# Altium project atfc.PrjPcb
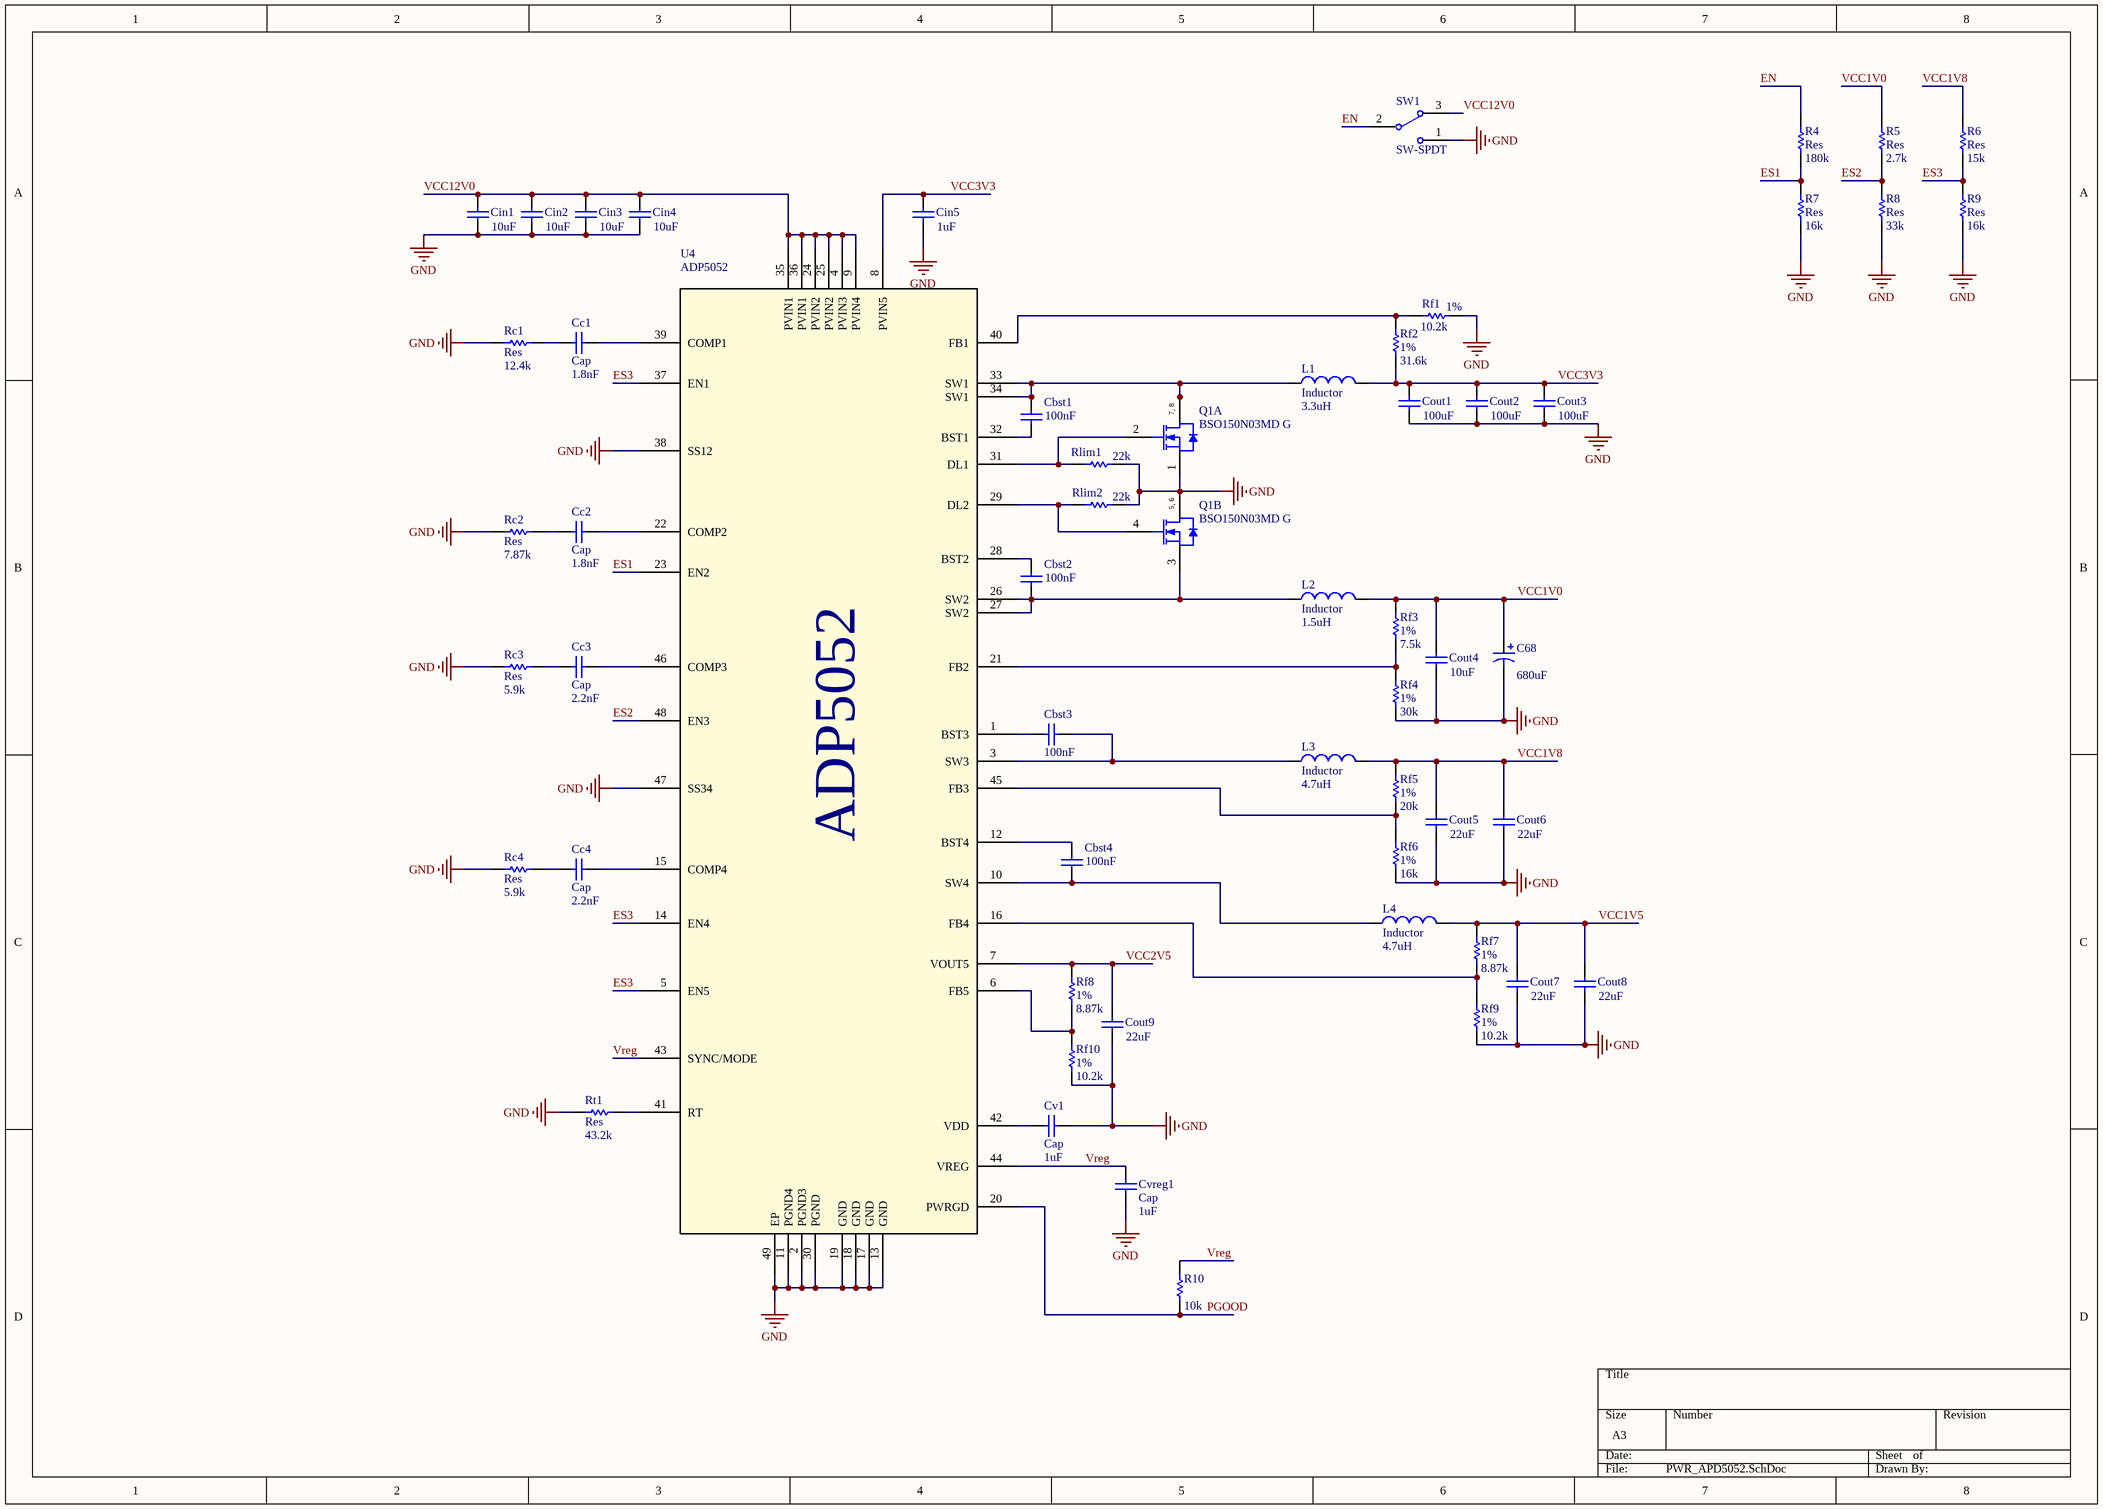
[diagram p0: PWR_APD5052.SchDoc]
9 sheets, 225 parts. Net scope: global (net labels, ports and power ports of the same name join across sheets).
Board file: atfc.PcbDoc
Sheets:
  PWR_APD5052.SchDoc
  FPGA_PWR.SchDoc
  SFP.SchDoc
  IO.SchDoc
  FMC.SchDoc
  FPGA_Banks1.SchDoc
  FPGA_Banks2.SchDoc
  Regulators.SchDoc
  Config.SchDoc

## Sheet PWR_APD5052.SchDoc
size A3

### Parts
C68  value 680uF  [C0805]  (hidden comment: Cap Pol3)
Cbst1  value 100nF  [C0402]  (hidden comment: Cap)
Cbst2  value 100nF  [C0402]  (hidden comment: Cap)
Cbst3  value 100nF  [C0402]  (hidden comment: Cap)
Cbst4  value 100nF  [C0402]  (hidden comment: Cap)
Cc1  Cap  value 1.8nF  [C0805]
Cc2  Cap  value 1.8nF  [C0805]
Cc3  Cap  value 2.2nF  [C0805]
Cc4  Cap  value 2.2nF  [C0805]
Cin1  value 10uF  [C0805]
Cin2  value 10uF  [C0805]
Cin3  value 10uF  [C0805]  (hidden comment: Cap)
Cin4  value 10uF  [C1210]  (hidden comment: Cap)
Cin5  value 1uF  [C0603]
Cout1  value 100uF  [C1210]  (hidden comment: Cap)
Cout2  value 100uF  [C1210]  (hidden comment: Cap)
Cout3  value 100uF  [C1210]  (hidden comment: Cap)
Cout4  value 10uF  [C1210]  (hidden comment: Cap)
Cout5  value 22uF  [C1210]  (hidden comment: Cap)
Cout6  value 22uF  [C1210]  (hidden comment: Cap)
Cout7  value 22uF  [C1210]  (hidden comment: Cap)
Cout8  value 22uF  [C1210]  (hidden comment: Cap)
Cout9  value 22uF  [C1210]  (hidden comment: Cap)
Cv1  Cap  value 1uF  [C0402]
Cvreg1  Cap  value 1uF  [C0402]
L1  Inductor  value 3.3uH  [MSS1048]
L2  Inductor  value 1.5uH  [MSS1048]
L3  Inductor  value 4.7uH  [MSS1048]
L4  Inductor  value 4.7uH  [MSS1048]
Q1  BSO150N03MD G  [INF-PG-DSO-8-16_N]  (parts A,B of 2)
R4  Res  value 180k  [R0603]
R5  Res  value 2.7k  [R0603]
R6  Res  value 15k  [R0603]
R7  Res  value 16k  [R0603]
R8  Res  value 33k  [R0603]
R9  Res  value 16k  [R0603]
R10  value 10k  [R0402]  (hidden comment: Res)
Rc1  Res  value 12.4k  [R0805]
Rc2  Res  value 7.87k  [R0805]
Rc3  Res  value 5.9k  [R0805]
Rc4  Res  value 5.9k  [R0805]
Rf1  value 10.2k  Tolerance: 1%  [R0402]  (hidden comment: Res)
Rf2  value 31.6k  Tolerance: 1%  [R0402]  (hidden comment: Res)
Rf3  value 7.5k  Tolerance: 1%  [R0402]  (hidden comment: Res)
Rf4  value 30k  Tolerance: 1%  [R0402]  (hidden comment: Res)
Rf5  value 20k  Tolerance: 1%  [R0402]  (hidden comment: Res)
Rf6  value 16k  Tolerance: 1%  [R0402]  (hidden comment: Res)
Rf7  value 8.87k  Tolerance: 1%  [R0402]  (hidden comment: Res)
Rf8  value 8.87k  Tolerance: 1%  [R0402]  (hidden comment: Res)
Rf9  value 10.2k  Tolerance: 1%  [R0402]  (hidden comment: Res)
Rf10  value 10.2k  Tolerance: 1%  [R0402]  (hidden comment: Res)
Rlim1  value 22k  [R0805]  (hidden comment: Res)
Rlim2  value 22k  [R0805]  (hidden comment: Res)
Rt1  Res  value 43.2k  [R0805]
SW1  SW-SPDT  [TL36WW15050]
U4  ADP5052  [CP_48_13]

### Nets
GND: C68.2 Cin1.1 Cin2.1 Cin3.1 Cin4.1 Cin5.1 Cout1.1 Cout2.1 Cout3.1 Cout4.1 Cout5.1 Cout6.1 Cout7.1 Cout8.1 Cout9.1 Cv1.1 Cvreg1.1 Q1.1(S1) Q1.5(D2) Q1.6(D2) R7.1 R8.1 R9.1 Rc1.1 Rc2.1 Rc3.1 Rc4.1 Rf1.2 Rf4.1 Rf6.1 Rf9.1 Rf10.1 Rlim1.2 Rlim2.2 Rt1.1 SW1.1 U4.2(PGND3) U4.11(PGND4) U4.13(GND) U4.17(GND) U4.18(GND) U4.19(GND) U4.30(PGND) U4.38(SS12) U4.47(SS34) U4.49(EP)
EN: R4.2 SW1.2
ES1: R4.1 R7.2 U4.23(EN2)
ES2: R5.1 R8.2 U4.48(EN3)
ES3: R6.1 R9.2 U4.5(EN5) U4.14(EN4) U4.37(EN1)
PGOOD: R10.1 U4.20(PWRGD)
VCC1V0: C68.1 Cout4.2 L2.2 R5.2 Rf3.2
VCC1V5: Cout7.2 Cout8.2 L4.2 Rf7.2
VCC1V8: Cout5.2 Cout6.2 L3.2 R6.2 Rf5.2
VCC2V5: Cout9.2 Rf8.2 U4.7(VOUT5)
VCC3V3: Cin5.2 Cout1.2 Cout2.2 Cout3.2 L1.2 Rf2.1 U4.8(PVIN5)
VCC12V0: Cin1.2 Cin2.2 Cin3.2 Cin4.2 SW1.3 U4.4(PVIN3) U4.9(PVIN4) U4.24(PVIN2) U4.25(PVIN2) U4.35(PVIN1) U4.36(PVIN1)
Vreg: Cvreg1.2 R10.2 U4.43(SYNC/MODE) U4.44(VREG)
NetCbst1_1: Cbst1.1 U4.32(BST1)
NetCbst1_2: Cbst1.2 L1.1 Q1.7(D1) Q1.8(D1) U4.33(SW1) U4.34(SW1)
NetCbst2_1: Cbst2.1 L2.1 Q1.3(S2) U4.26(SW2) U4.27(SW2)
NetCbst2_2: Cbst2.2 U4.28(BST2)
NetCbst3_1: Cbst3.1 L3.1 U4.3(SW3)
NetCbst3_2: Cbst3.2 U4.1(BST3)
NetCbst4_1: Cbst4.1 L4.1 U4.10(SW4)
NetCbst4_2: Cbst4.2 U4.12(BST4)
NetCc1_1: Cc1.1 Rc1.2
NetCc1_2: Cc1.2 U4.39(COMP1)
NetCc2_1: Cc2.1 Rc2.2
NetCc2_2: Cc2.2 U4.22(COMP2)
NetCc3_1: Cc3.1 Rc3.2
NetCc3_2: Cc3.2 U4.46(COMP3)
NetCc4_1: Cc4.1 Rc4.2
NetCc4_2: Cc4.2 U4.15(COMP4)
NetCv1_2: Cv1.2 U4.42(VDD)
NetQ1_2: Q1.2(G1) Rlim1.1 U4.31(DL1)
NetQ1_4: Q1.4(G2) Rlim2.1 U4.29(DL2)
NetRf1_1: Rf1.1 Rf2.2 U4.40(FB1)
NetRf3_1: Rf3.1 Rf4.2 U4.21(FB2)
NetRf5_1: Rf5.1 Rf6.2 U4.45(FB3)
NetRf7_1: Rf7.1 Rf9.2 U4.16(FB4)
NetRf8_1: Rf8.1 Rf10.2 U4.6(FB5)
NetRt1_2: Rt1.2 U4.41(RT)

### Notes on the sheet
- (near U4) ADP5052

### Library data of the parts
C68 = Cap Pol3: Polarized Capacitor (Surface Mount)
Cbst1-Cbst4 Cc1-Cc4 Cin1-Cin5 Cout1-Cout9 Cv1 Cvreg1 = Cap: Capacitor
L1-L4 = Inductor: Code_IEC: 1005
Q1 = BSO150N03MD G: N-Channel OptiMOS 3 M-Series Power-MOSFET, 30 V VDS, 9.3 A ID, -55 to 150 degC, PG-DSO-8-16, Reel, Green; Manufacturer: Infineon; Green: TRUE; ID (max): 9.3 A; IDpuls (max): 65 A; Polarity: N; Ptot (max): 2 W; QG: 6.1 nC; RDS (on) (max): 15 mOhm; RDS (on) (max) (@4.5V): 18.2 mOhm; Rth: 50 K/W; RthJA (max): 150 K/W; VDS (max): 30 V; VGS(th) (max): 2 V; VGS(th) (min): 1 V
R4-R10 Rc1-Rc4 Rf1-Rf10 Rlim1 Rlim2 Rt1 = Res: Resistor
SW1 = SW-SPDT: SPDT Subminiature Toggle Switch, Right Angle Mounting, Vertical Actuation
U4 = ADP5052ACPZ-R7: Imported

## Sheet FPGA_PWR.SchDoc
size A4
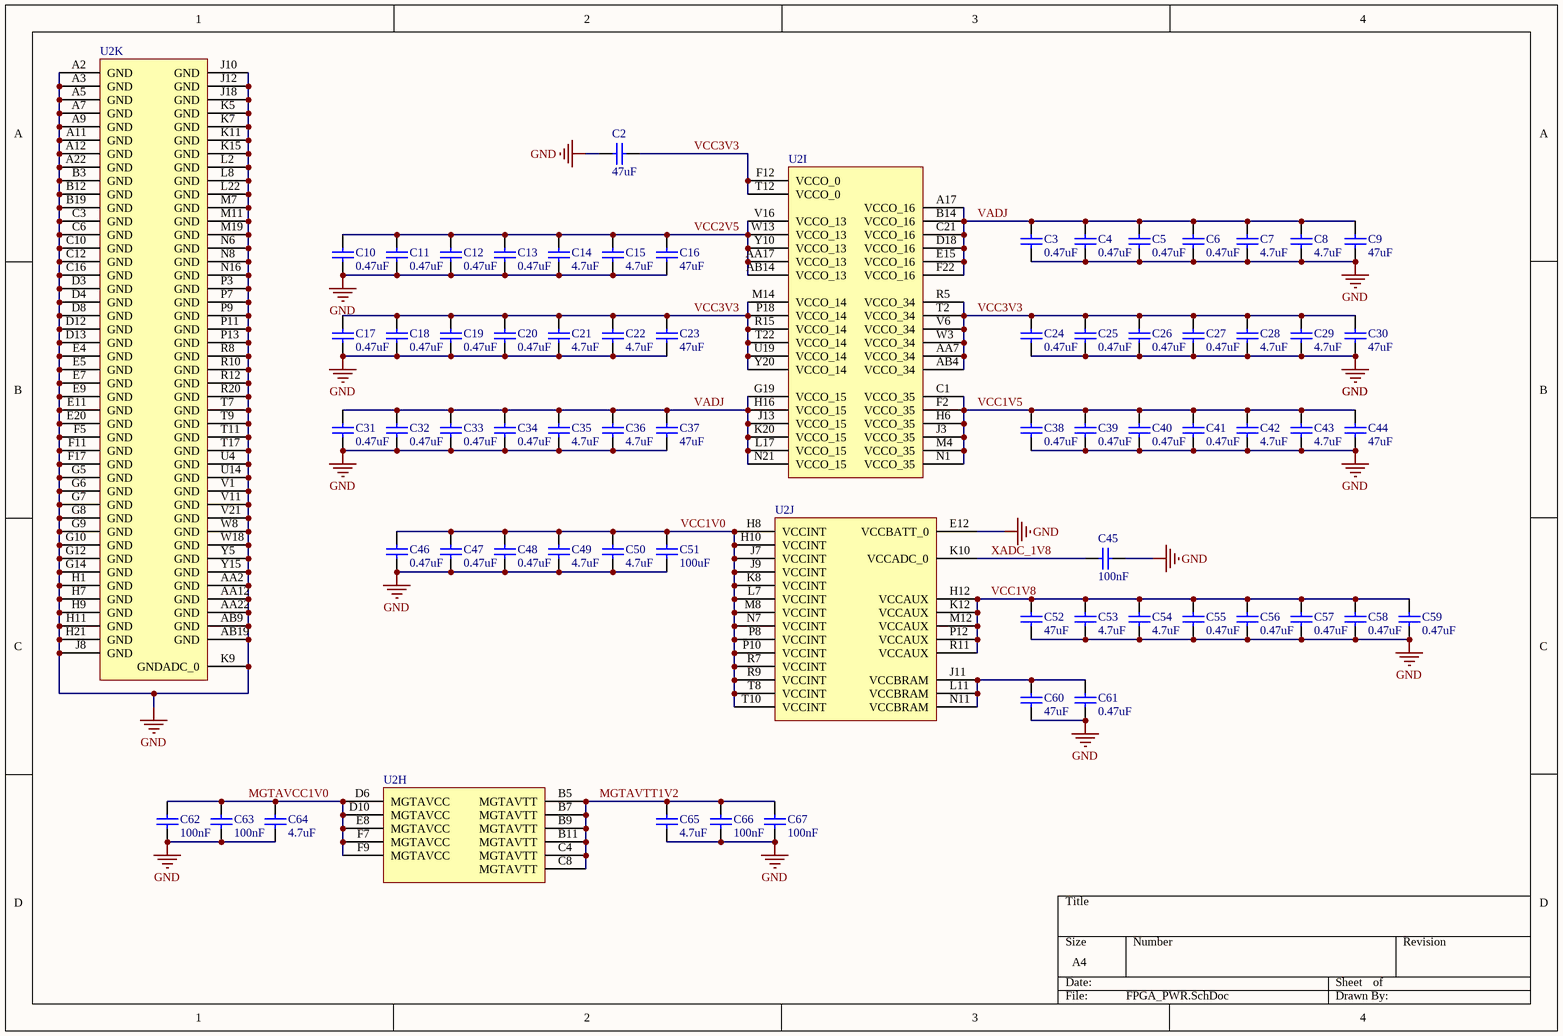
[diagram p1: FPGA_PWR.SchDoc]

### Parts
C2  value 47uF  [C1210]  (hidden comment: Cap)
C3  value 0.47uF  [C0603]  (hidden comment: Cap)
C4  value 0.47uF  [C0603]  (hidden comment: Cap)
C5  value 0.47uF  [C0603]  (hidden comment: Cap)
C6  value 0.47uF  [C0603]  (hidden comment: Cap)
C7  value 4.7uF  [C0805]  (hidden comment: Cap)
C8  value 4.7uF  [C0805]  (hidden comment: Cap)
C9  value 47uF  [C1210]  (hidden comment: Cap)
C10  value 0.47uF  [C0603]  (hidden comment: Cap)
C11  value 0.47uF  [C0603]  (hidden comment: Cap)
C12  value 0.47uF  [C0603]  (hidden comment: Cap)
C13  value 0.47uF  [C0603]  (hidden comment: Cap)
C14  value 4.7uF  [C0805]  (hidden comment: Cap)
C15  value 4.7uF  [C0805]  (hidden comment: Cap)
C16  value 47uF  [C1210]  (hidden comment: Cap)
C17  value 0.47uF  [C0603]  (hidden comment: Cap)
C18  value 0.47uF  [C0603]  (hidden comment: Cap)
C19  value 0.47uF  [C0603]  (hidden comment: Cap)
C20  value 0.47uF  [C0603]  (hidden comment: Cap)
C21  value 4.7uF  [C0805]  (hidden comment: Cap)
C22  value 4.7uF  [C0805]  (hidden comment: Cap)
C23  value 47uF  [C1210]  (hidden comment: Cap)
C24  value 0.47uF  [C0603]  (hidden comment: Cap)
C25  value 0.47uF  [C0603]  (hidden comment: Cap)
C26  value 0.47uF  [C0603]  (hidden comment: Cap)
C27  value 0.47uF  [C0603]  (hidden comment: Cap)
C28  value 4.7uF  [C0805]  (hidden comment: Cap)
C29  value 4.7uF  [C0805]  (hidden comment: Cap)
C30  value 47uF  [C1210]  (hidden comment: Cap)
C31  value 0.47uF  [C0603]  (hidden comment: Cap)
C32  value 0.47uF  [C0603]  (hidden comment: Cap)
C33  value 0.47uF  [C0603]  (hidden comment: Cap)
C34  value 0.47uF  [C0603]  (hidden comment: Cap)
C35  value 4.7uF  [C0805]  (hidden comment: Cap)
C36  value 4.7uF  [C0805]  (hidden comment: Cap)
C37  value 47uF  [C1210]  (hidden comment: Cap)
C38  value 0.47uF  [C0603]  (hidden comment: Cap)
C39  value 0.47uF  [C0603]  (hidden comment: Cap)
C40  value 0.47uF  [C0603]  (hidden comment: Cap)
C41  value 0.47uF  [C0603]  (hidden comment: Cap)
C42  value 4.7uF  [C0805]  (hidden comment: Cap)
C43  value 4.7uF  [C0805]  (hidden comment: Cap)
C44  value 47uF  [C1210]  (hidden comment: Cap)
C45  value 100nF  [C0603]  (hidden comment: Cap)
C46  value 0.47uF  [C0603]  (hidden comment: Cap)
C47  value 0.47uF  [C0603]  (hidden comment: Cap)
C48  value 0.47uF  [C0603]  (hidden comment: Cap)
C49  value 4.7uF  [C0805]  (hidden comment: Cap)
C50  value 4.7uF  [C0805]  (hidden comment: Cap)
C51  value 100uF  [C1210]  (hidden comment: Cap)
C52  value 47uF  [C1210]  (hidden comment: Cap)
C53  value 4.7uF  [C0805]  (hidden comment: Cap)
C54  value 4.7uF  [C0805]  (hidden comment: Cap)
C55  value 0.47uF  [C0603]  (hidden comment: Cap)
C56  value 0.47uF  [C0603]  (hidden comment: Cap)
C57  value 0.47uF  [C0603]  (hidden comment: Cap)
C58  value 0.47uF  [C0603]  (hidden comment: Cap)
C59  value 0.47uF  [C0603]  (hidden comment: Cap)
C60  value 47uF  [C1210]  (hidden comment: Cap)
C61  value 0.47uF  [C0603]  (hidden comment: Cap)
C62  value 100nF  [C0402]  (hidden comment: Cap)
C63  value 100nF  [C0402]  (hidden comment: Cap)
C64  value 4.7uF  [C0805]  (hidden comment: Cap)
C65  value 4.7uF  [C0805]  (hidden comment: Cap)
C66  value 100nF  [C0402]  (hidden comment: Cap)
C67  value 100nF  [C0402]  (hidden comment: Cap)
U2  (no value)  [FGG484]  (parts H,I,J,K of 12)

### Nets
GND: C2.2 C3.2 C4.2 C5.2 C6.2 C7.2 C8.2 C9.2 C10.2 C11.2 C12.2 C13.2 C14.2 C15.2 C16.2 C17.2 C18.2 C19.2 C20.2 C21.2 C22.2 C23.2 C24.2 C25.2 C26.2 C27.2 C28.2 C29.2 C30.2 C31.2 C32.2 C33.2 C34.2 C35.2 C36.2 C37.2 C38.2 C39.2 C40.2 C41.2 C42.2 C43.2 C44.2 C45.1 C46.2 C47.2 C48.2 C49.2 C50.2 C51.2 C52.2 C53.2 C54.2 C55.2 C56.2 C57.2 C58.2 C59.2 C60.2 C61.2 C62.2 C63.2 C64.2 C65.1 C66.1 C67.1 U2.A2(GND) U2.A3(GND) U2.A5(GND) U2.A7(GND) U2.A9(GND) U2.A11(GND) U2.A12(GND) U2.A22(GND) U2.AA2(GND) U2.AA12(GND) U2.AA22(GND) U2.AB9(GND) U2.AB19(GND) U2.B3(GND) U2.B12(GND) U2.B19(GND) U2.C3(GND) U2.C6(GND) U2.C10(GND) U2.C12(GND) U2.C16(GND) U2.D3(GND) U2.D4(GND) U2.D8(GND) U2.D12(GND) U2.D13(GND) U2.E4(GND) U2.E5(GND) U2.E7(GND) U2.E9(GND) U2.E11(GND) U2.E12(VCCBATT_0) U2.E20(GND) U2.F5(GND) U2.F11(GND) U2.F17(GND) U2.G5(GND) U2.G6(GND) U2.G7(GND) U2.G8(GND) U2.G9(GND) U2.G10(GND) U2.G12(GND) U2.G14(GND) U2.H1(GND) U2.H7(GND) U2.H9(GND) U2.H11(GND) U2.H21(GND) U2.J8(GND) U2.J10(GND) U2.J12(GND) U2.J18(GND) U2.K5(GND) U2.K7(GND) U2.K9(GNDADC_0) U2.K11(GND) U2.K15(GND) U2.L2(GND) U2.L8(GND) U2.L22(GND) U2.M7(GND) U2.M11(GND) U2.M19(GND) U2.N6(GND) U2.N8(GND) U2.N16(GND) U2.P3(GND) U2.P7(GND) U2.P9(GND) U2.P11(GND) U2.P13(GND) U2.R8(GND) U2.R10(GND) U2.R12(GND) U2.R20(GND) U2.T7(GND) U2.T9(GND) U2.T11(GND) U2.T17(GND) U2.U4(GND) U2.U14(GND) U2.V1(GND) U2.V11(GND) U2.V21(GND) U2.W8(GND) U2.W18(GND) U2.Y5(GND) U2.Y15(GND)
MGTAVCC1V0: C62.1 C63.1 C64.1 U2.D6(MGTAVCC) U2.D10(MGTAVCC) U2.E8(MGTAVCC) U2.F7(MGTAVCC) U2.F9(MGTAVCC)
MGTAVTT1V2: C65.2 C66.2 C67.2 U2.B5(MGTAVTT) U2.B7(MGTAVTT) U2.B9(MGTAVTT) U2.B11(MGTAVTT) U2.C4(MGTAVTT) U2.C8(MGTAVTT)
VADJ: C3.1 C4.1 C5.1 C6.1 C7.1 C8.1 C9.1 C31.1 C32.1 C33.1 C34.1 C35.1 C36.1 C37.1 U2.A17(VCCO_16) U2.B14(VCCO_16) U2.C21(VCCO_16) U2.D18(VCCO_16) U2.E15(VCCO_16) U2.F22(VCCO_16) U2.G19(VCCO_15) U2.H16(VCCO_15) U2.J13(VCCO_15) U2.K20(VCCO_15) U2.L17(VCCO_15) U2.N21(VCCO_15)
VCC1V0: C46.1 C47.1 C48.1 C49.1 C50.1 C51.1 U2.H8(VCCINT) U2.H10(VCCINT) U2.J7(VCCINT) U2.J9(VCCINT) U2.K8(VCCINT) U2.L7(VCCINT) U2.M8(VCCINT) U2.N7(VCCINT) U2.P8(VCCINT) U2.P10(VCCINT) U2.R7(VCCINT) U2.R9(VCCINT) U2.T8(VCCINT) U2.T10(VCCINT)
VCC1V5: C38.1 C39.1 C40.1 C41.1 C42.1 C43.1 C44.1 U2.C1(VCCO_35) U2.F2(VCCO_35) U2.H6(VCCO_35) U2.J3(VCCO_35) U2.M4(VCCO_35) U2.N1(VCCO_35)
VCC1V8: C52.1 C53.1 C54.1 C55.1 C56.1 C57.1 C58.1 C59.1 U2.H12(VCCAUX) U2.K12(VCCAUX) U2.M12(VCCAUX) U2.P12(VCCAUX) U2.R11(VCCAUX)
VCC2V5: C10.1 C11.1 C12.1 C13.1 C14.1 C15.1 C16.1 U2.AA17(VCCO_13) U2.AB14(VCCO_13) U2.V16(VCCO_13) U2.W13(VCCO_13) U2.Y10(VCCO_13)
VCC3V3: C2.1 C17.1 C18.1 C19.1 C20.1 C21.1 C22.1 C23.1 C24.1 C25.1 C26.1 C27.1 C28.1 C29.1 C30.1 U2.AA7(VCCO_34) U2.AB4(VCCO_34) U2.F12(VCCO_0) U2.M14(VCCO_14) U2.P18(VCCO_14) U2.R5(VCCO_34) U2.R15(VCCO_14) U2.T2(VCCO_34) U2.T12(VCCO_0) U2.T22(VCCO_14) U2.U19(VCCO_14) U2.V6(VCCO_34) U2.W3(VCCO_34) U2.Y20(VCCO_14)
XADC_1V8: C45.2 U2.K10(VCCADC_0)
NetC60_1: C60.1 C61.1 U2.J11(VCCBRAM) U2.L11(VCCBRAM) U2.N11(VCCBRAM)

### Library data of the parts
C2-C67 = Cap: Capacitor
U2 = XC7A35T-1FGG484C: Artix-7 FPGA, 250 User I/Os, 4 GTP, 484-Ball BGA, Speed Grade 1, Commercial Grade, Pb-Free; Manufacturer: Xilinx; Total Block RAM: 1800 Kb; GTP: 4; Clock Mgmt Tiles (CMTs): 5; Logic Cells: 33280; Available User I/O: 250; Speed Grades: 1

## Sheet SFP.SchDoc
size A4
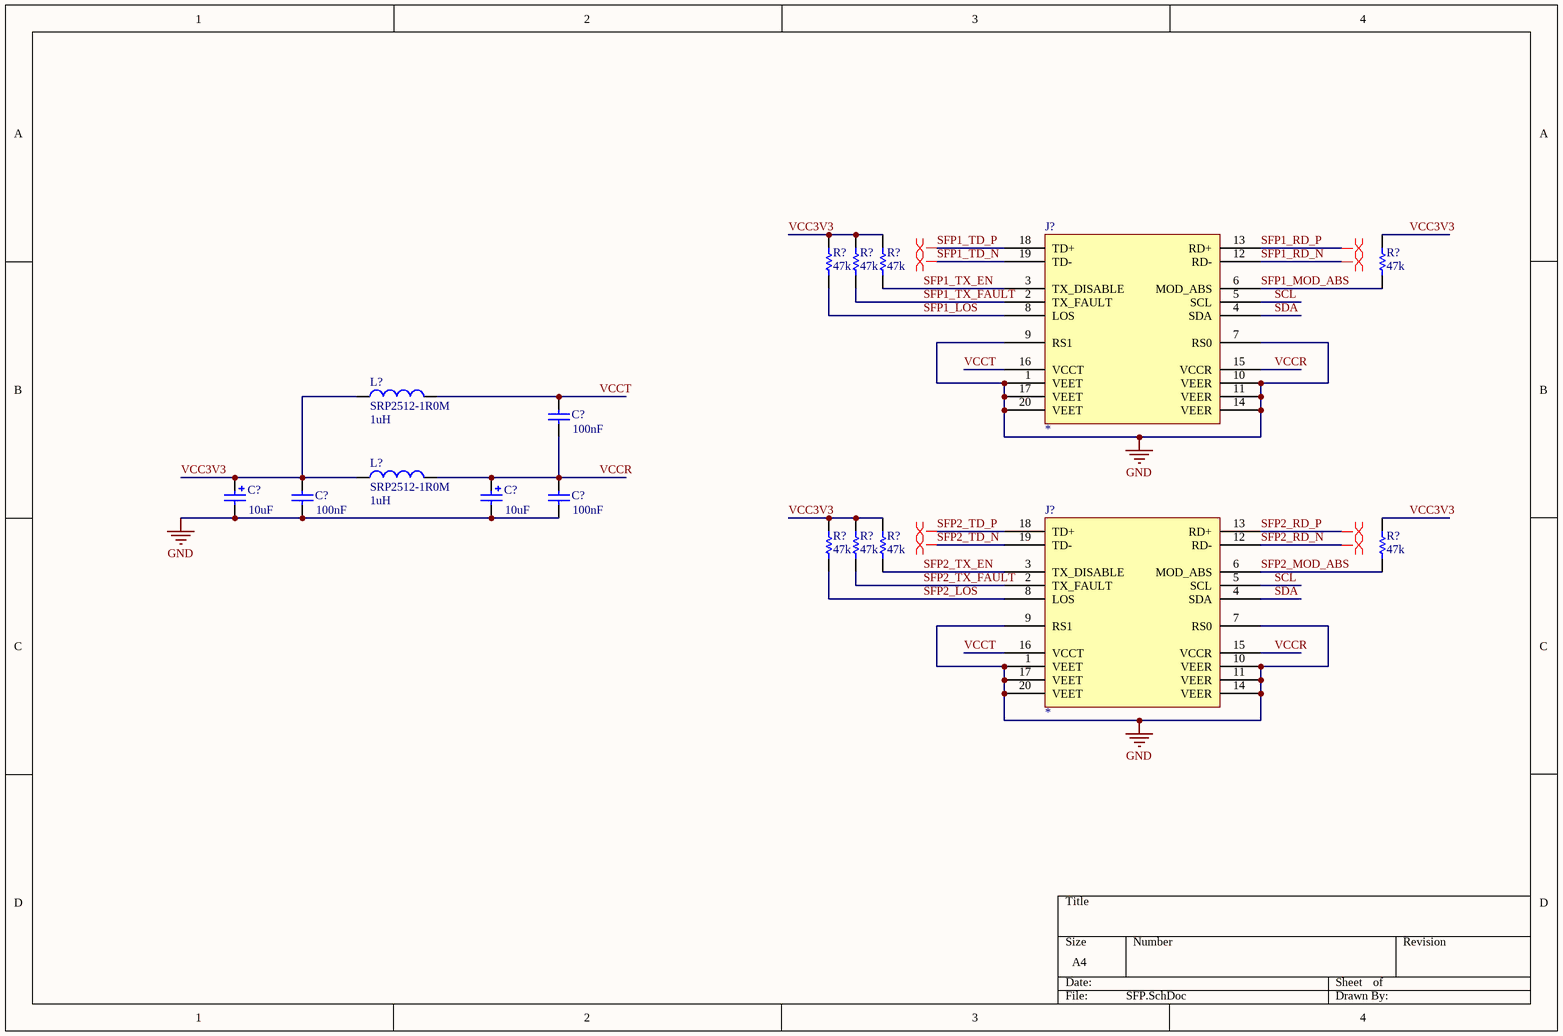
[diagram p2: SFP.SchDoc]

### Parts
(Parts that share a designator on the sheet are numbered #1, #2 ... from top to bottom, then left to right.)
C?#1  value 100nF  [C0402]  (hidden comment: Cap)
C?#2  value 10uF  [C1206_P]
C?#3  value 10uF  [C1206_P]
C?#4  value 100nF  [C0402]  (hidden comment: Cap)
C?#5  value 100nF  [C0402]  (hidden comment: Cap)
J2  *  [SFP+20]
J?  *  [SFP+20]
L?#1  SRP2512-1R0M  value 1uH  [SRP2512]
L?#2  SRP2512-1R0M  value 1uH  [SRP2512]
R?#1  value 47k  [R0402]  (hidden comment: Res)
R?#2  value 47k  [R0402]  (hidden comment: Res)
R?#3  value 47k  [R0402]  (hidden comment: Res)
R?#4  value 47k  [R0402]  (hidden comment: Res)
R?#5  value 47k  [R0402]  (hidden comment: Res)
R?#6  value 47k  [R0402]  (hidden comment: Res)
R?#7  value 47k  [R0402]  (hidden comment: Res)
R?#8  value 47k  [R0402]  (hidden comment: Res)

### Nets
GND: C?#2.2 C?#3.2 C?#4.1 C?#5.1 J2.1(VEET) J2.7(RS0) J2.9(RS1) J2.10(VEER) J2.11(VEER) J2.14(VEER) J2.17(VEET) J2.20(VEET) J?.1(VEET) J?.7(RS0) J?.9(RS1) J?.10(VEER) J?.11(VEER) J?.14(VEER) J?.17(VEET) J?.20(VEET)
SCL: J2.5(SCL) J?.5(SCL)
SDA: J2.4(SDA) J?.4(SDA)
SFP1_LOS: J2.8(LOS) R?#1.2
SFP1_MOD_ABS: J2.6(MOD_ABS) R?#4.2
SFP1_RD_N: J2.12(RD-)
SFP1_RD_P: J2.13(RD+)
SFP1_TD_N: J2.19(TD-)
SFP1_TD_P: J2.18(TD+)
SFP1_TX_EN: J2.3(TX_DISABLE) R?#3.2
SFP1_TX_FAULT: J2.2(TX_FAULT) R?#2.2
SFP2_LOS: J?.8(LOS) R?#5.2
SFP2_MOD_ABS: J?.6(MOD_ABS) R?#8.2
SFP2_RD_N: J?.12(RD-)
SFP2_RD_P: J?.13(RD+)
SFP2_TD_N: J?.19(TD-)
SFP2_TD_P: J?.18(TD+)
SFP2_TX_EN: J?.3(TX_DISABLE) R?#7.2
SFP2_TX_FAULT: J?.2(TX_FAULT) R?#6.2
VCC3V3: C?#2.1 C?#4.2 L?#1.1 L?#2.1 R?#1.1 R?#2.1 R?#3.1 R?#4.1 R?#5.1 R?#6.1 R?#7.1 R?#8.1
VCCR: C?#1.1 C?#3.1 C?#5.2 J2.15(VCCR) J?.15(VCCR) L?#2.2
VCCT: C?#1.2 J2.16(VCCT) J?.16(VCCT) L?#1.2

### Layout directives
differential pair: SFP1_RD_N, SFP1_RD_P, SFP1_TD_N, SFP1_TD_P, SFP2_RD_N, SFP2_RD_P, SFP2_TD_N, SFP2_TD_P

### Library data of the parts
C?#1 C?#4 C?#5 = Cap: Capacitor
C?#2 C?#3 = Cap Pol: Polarized Capacitor (Surface Mount)
J2 J? = SFP+
L?#1 L?#2 = Inductor: Code_IEC: 1005
R?#1-R?#8 = Res: Resistor

## Sheet IO.SchDoc
size A4
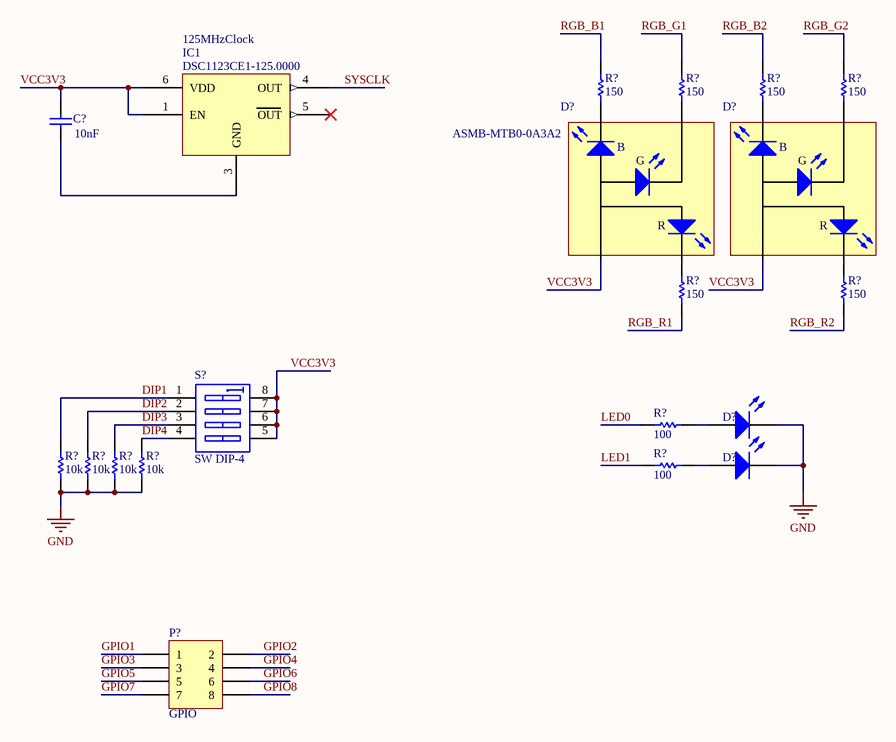
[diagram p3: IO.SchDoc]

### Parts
(Parts that share a designator on the sheet are numbered #1, #2 ... from top to bottom, then left to right.)
C?#6  value 10nF  [C0402]  (hidden comment: Cap)
D?#1  ASMB-MTB0-0A3A2  [ASMB-MTB0-0A3A2]
D?#2  ASMB-MTB0-0A3A2  [ASMB-MTB0-0A3A2]  (value not drawn)
D?#3  LED  (value not drawn)
D?#4  LED  (value not drawn)
IC1  DSC1123CE1-125.0000  [DSC1123_32_25]
P?#1  GPIO  [HDR2X4]
R?#9  value 150  [R0603]  (hidden comment: Res)
R?#10  value 150  [R0603]  (hidden comment: Res)
R?#11  value 150  [R0603]  (hidden comment: Res)
R?#12  value 150  [R0603]  (hidden comment: Res)
R?#13  value 150  [R0603]  (hidden comment: Res)
R?#14  value 150  [R0603]  (hidden comment: Res)
R?#15  value 100  [R0603]  (hidden comment: Res)
R?#16  value 10k  [R0402]  (hidden comment: Res)
R?#17  value 10k  [R0402]  (hidden comment: Res)
R?#18  value 10k  [R0402]  (hidden comment: Res)
R?#19  value 10k  [R0402]  (hidden comment: Res)
R?#20  value 100  [R0603]  (hidden comment: Res)
S?  SW DIP-4  [SO8_N]

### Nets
GND: D?#3.2(K) D?#4.2(K) R?#16.2 R?#17.2 R?#18.2 R?#19.2
DIP1: R?#16.1 S?.1(A1)
DIP2: R?#17.1 S?.2(A2)
DIP3: R?#18.1 S?.3(A3)
DIP4: R?#19.1 S?.4(A4)
GPIO1: P?#1.1
GPIO2: P?#1.2
GPIO3: P?#1.3
GPIO4: P?#1.4
GPIO5: P?#1.5
GPIO6: P?#1.6
GPIO7: P?#1.7
GPIO8: P?#1.8
LED0: R?#15.2
LED1: R?#20.2
RGB_B1: R?#9.2
RGB_B2: R?#11.2
RGB_G1: R?#10.2
RGB_G2: R?#12.2
RGB_R1: R?#13.1
RGB_R2: R?#14.1
SYSCLK: IC1.4(OUT)
VCC3V3: C?#6.2 D?#1.1(A) D?#2.1(A) IC1.1(EN) IC1.6(VDD) S?.5(B4) S?.6(B3) S?.7(B2) S?.8(B1)
NetC?#6_1: C?#6.1 IC1.3(GND)
NetD?#1_2: D?#1.2(B) R?#9.1
NetD?#1_3: D?#1.3(G) R?#10.1
NetD?#1_4: D?#1.4(R) R?#13.2
NetD?#2_2: D?#2.2(B) R?#11.1
NetD?#2_3: D?#2.3(G) R?#12.1
NetD?#2_4: D?#2.4(R) R?#14.2
NetD?#3_1: D?#3.1(A) R?#15.1
NetD?#4_1: D?#4.1(A) R?#20.1

Not connected (* = marked no-connect by the designer): IC1 5(OUT)*

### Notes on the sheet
- (near IC1) 125MHzClock

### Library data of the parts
C?#6 = Cap: Capacitor
D?#1 D?#2 = LED_RGB: Typical INFRARED GaAs LED
IC1 = DSC1123CE1-125: Standard Clock Oscillators Oscillator Hi Perf -20C-70C 50ppm
P?#1 = Header 4X2: Header, 4-Pin, Dual row
R?#9-R?#20 = Res: Resistor
S? = SW DIP-4: DIP Switch, 4 Position, SPST

## Sheet FMC.SchDoc
size A4
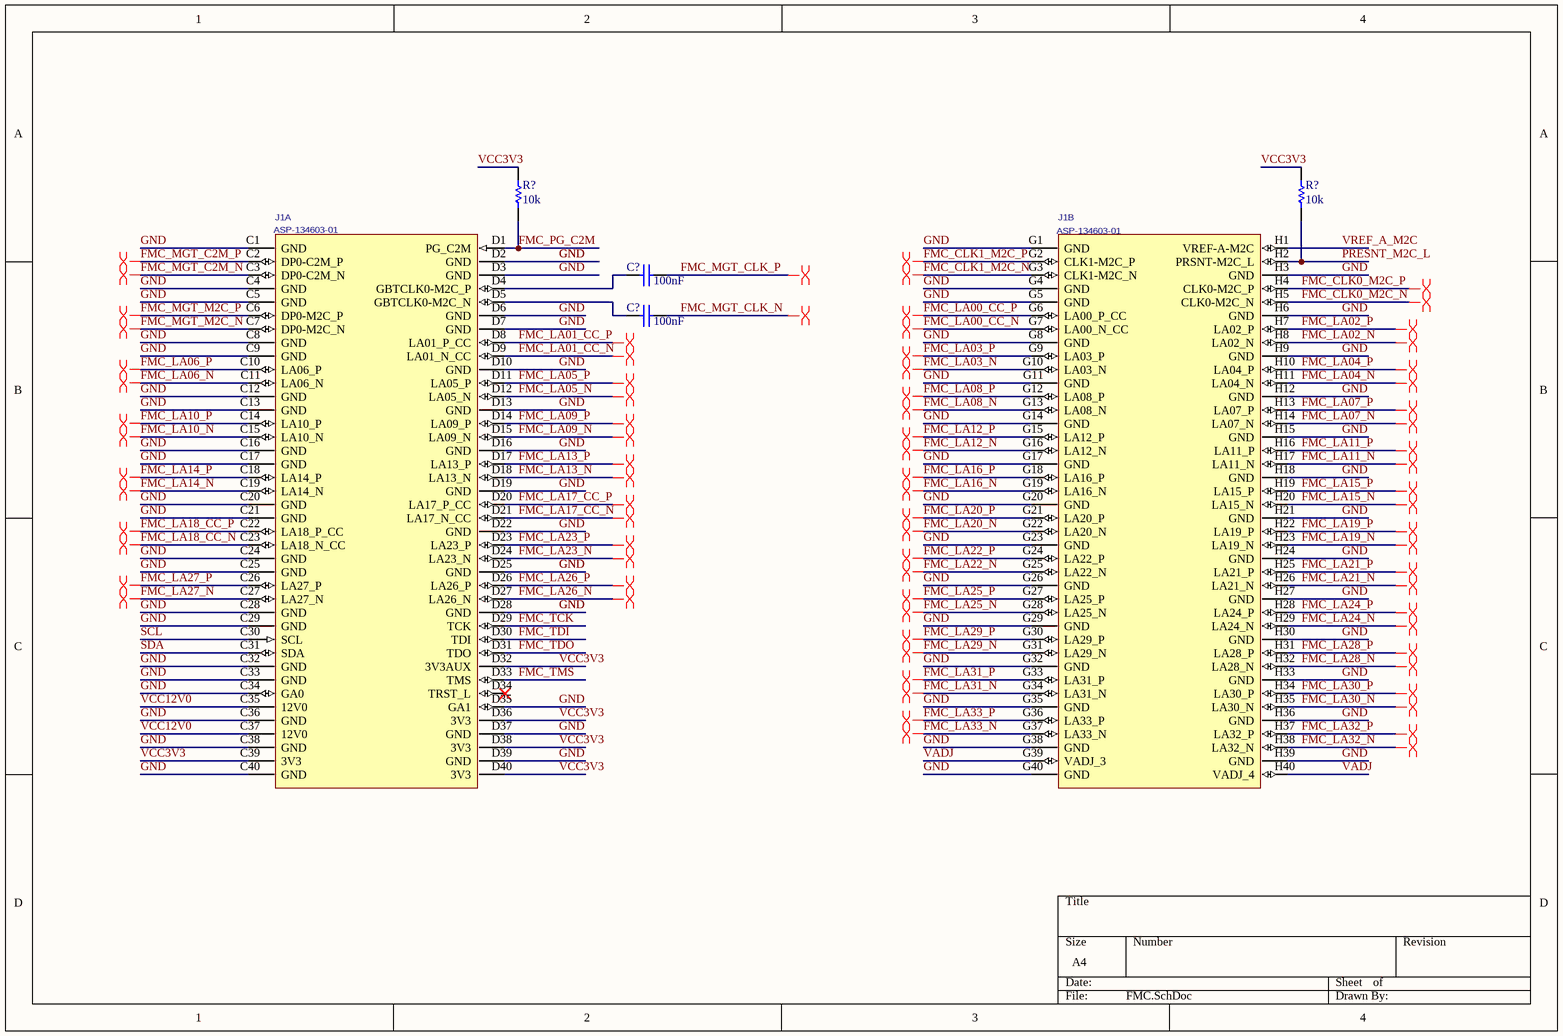
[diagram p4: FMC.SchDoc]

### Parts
(Parts that share a designator on the sheet are numbered #1, #2 ... from top to bottom, then left to right.)
C?#7  value 100nF  [C0402]  (hidden comment: Cap)
C?#8  value 100nF  [C0402]  (hidden comment: Cap)
J1  ASP-134603-01  [ASP-134603-01]  (parts A,B of 2)
R?#21  value 10k  [R0402]  (hidden comment: Res)
R?#22  value 10k  [R0402]  (hidden comment: Res)

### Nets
GND: J1.C1(GND) J1.C4(GND) J1.C5(GND) J1.C8(GND) J1.C9(GND) J1.C12(GND) J1.C13(GND) J1.C16(GND) J1.C17(GND) J1.C20(GND) J1.C21(GND) J1.C24(GND) J1.C25(GND) J1.C28(GND) J1.C29(GND) J1.C32(GND) J1.C33(GND) J1.C34(GA0) J1.C36(GND) J1.C38(GND) J1.C40(GND) J1.D2(GND) J1.D3(GND) J1.D6(GND) J1.D7(GND) J1.D10(GND) J1.D13(GND) J1.D16(GND) J1.D19(GND) J1.D22(GND) J1.D25(GND) J1.D28(GND) J1.D35(GA1) J1.D37(GND) J1.D39(GND) J1.G1(GND) J1.G4(GND) J1.G5(GND) J1.G8(GND) J1.G11(GND) J1.G14(GND) J1.G17(GND) J1.G20(GND) J1.G23(GND) J1.G26(GND) J1.G29(GND) J1.G32(GND) J1.G35(GND) J1.G38(GND) J1.G40(GND) J1.H3(GND) J1.H6(GND) J1.H9(GND) J1.H12(GND) J1.H15(GND) J1.H18(GND) J1.H21(GND) J1.H24(GND) J1.H27(GND) J1.H30(GND) J1.H33(GND) J1.H36(GND) J1.H39(GND)
FMC_CLK0_M2C_N: J1.H5(CLK0-M2C_N)
FMC_CLK0_M2C_P: J1.H4(CLK0-M2C_P)
FMC_CLK1_M2C_N: J1.G3(CLK1-M2C_N)
FMC_CLK1_M2C_P: J1.G2(CLK1-M2C_P)
FMC_LA00_CC_N: J1.G7(LA00_N_CC)
FMC_LA00_CC_P: J1.G6(LA00_P_CC)
FMC_LA01_CC_N: J1.D9(LA01_N_CC)
FMC_LA01_CC_P: J1.D8(LA01_P_CC)
FMC_LA02_N: J1.H8(LA02_N)
FMC_LA02_P: J1.H7(LA02_P)
FMC_LA03_N: J1.G10(LA03_N)
FMC_LA03_P: J1.G9(LA03_P)
FMC_LA04_N: J1.H11(LA04_N)
FMC_LA04_P: J1.H10(LA04_P)
FMC_LA05_N: J1.D12(LA05_N)
FMC_LA05_P: J1.D11(LA05_P)
FMC_LA06_N: J1.C11(LA06_N)
FMC_LA06_P: J1.C10(LA06_P)
FMC_LA07_N: J1.H14(LA07_N)
FMC_LA07_P: J1.H13(LA07_P)
FMC_LA08_N: J1.G13(LA08_N)
FMC_LA08_P: J1.G12(LA08_P)
FMC_LA09_N: J1.D15(LA09_N)
FMC_LA09_P: J1.D14(LA09_P)
FMC_LA10_N: J1.C15(LA10_N)
FMC_LA10_P: J1.C14(LA10_P)
FMC_LA11_N: J1.H17(LA11_N)
FMC_LA11_P: J1.H16(LA11_P)
FMC_LA12_N: J1.G16(LA12_N)
FMC_LA12_P: J1.G15(LA12_P)
FMC_LA13_N: J1.D18(LA13_N)
FMC_LA13_P: J1.D17(LA13_P)
FMC_LA14_N: J1.C19(LA14_N)
FMC_LA14_P: J1.C18(LA14_P)
FMC_LA15_N: J1.H20(LA15_N)
FMC_LA15_P: J1.H19(LA15_P)
FMC_LA16_N: J1.G19(LA16_N)
FMC_LA16_P: J1.G18(LA16_P)
FMC_LA17_CC_N: J1.D21(LA17_N_CC)
FMC_LA17_CC_P: J1.D20(LA17_P_CC)
FMC_LA18_CC_N: J1.C23(LA18_N_CC)
FMC_LA18_CC_P: J1.C22(LA18_P_CC)
FMC_LA19_N: J1.H23(LA19_N)
FMC_LA19_P: J1.H22(LA19_P)
FMC_LA20_N: J1.G22(LA20_N)
FMC_LA20_P: J1.G21(LA20_P)
FMC_LA21_N: J1.H26(LA21_N)
FMC_LA21_P: J1.H25(LA21_P)
FMC_LA22_N: J1.G25(LA22_N)
FMC_LA22_P: J1.G24(LA22_P)
FMC_LA23_N: J1.D24(LA23_N)
FMC_LA23_P: J1.D23(LA23_P)
FMC_LA24_N: J1.H29(LA24_N)
FMC_LA24_P: J1.H28(LA24_P)
FMC_LA25_N: J1.G28(LA25_N)
FMC_LA25_P: J1.G27(LA25_P)
FMC_LA26_N: J1.D27(LA26_N)
FMC_LA26_P: J1.D26(LA26_P)
FMC_LA27_N: J1.C27(LA27_N)
FMC_LA27_P: J1.C26(LA27_P)
FMC_LA28_N: J1.H32(LA28_N)
FMC_LA28_P: J1.H31(LA28_P)
FMC_LA29_N: J1.G31(LA29_N)
FMC_LA29_P: J1.G30(LA29_P)
FMC_LA30_N: J1.H35(LA30_N)
FMC_LA30_P: J1.H34(LA30_P)
FMC_LA31_N: J1.G34(LA31_N)
FMC_LA31_P: J1.G33(LA31_P)
FMC_LA32_N: J1.H38(LA32_N)
FMC_LA32_P: J1.H37(LA32_P)
FMC_LA33_N: J1.G37(LA33_N)
FMC_LA33_P: J1.G36(LA33_P)
FMC_MGT_C2M_N: J1.C3(DP0-C2M_N)
FMC_MGT_C2M_P: J1.C2(DP0-C2M_P)
FMC_MGT_CLK_N: C?#8.2
FMC_MGT_CLK_P: C?#7.2
FMC_MGT_M2C_N: J1.C7(DP0-M2C_N)
FMC_MGT_M2C_P: J1.C6(DP0-M2C_P)
FMC_PG_C2M: J1.D1(PG_C2M) R?#21.1
FMC_TCK: J1.D29(TCK)
FMC_TDI: J1.D30(TDI)
FMC_TDO: J1.D31(TDO)
FMC_TMS: J1.D33(TMS)
PRESNT_M2C_L: J1.H2(PRSNT-M2C_L) R?#22.1
SCL: J1.C30(SCL)
SDA: J1.C31(SDA)
VADJ: J1.G39(VADJ_3) J1.H40(VADJ_4)
VCC3V3: J1.C39(3V3) J1.D32(3V3AUX) J1.D36(3V3) J1.D38(3V3) J1.D40(3V3) R?#21.2 R?#22.2
VCC12V0: J1.C35(12V0) J1.C37(12V0)
VREF_A_M2C: J1.H1(VREF-A-M2C)
NetC?#7_1: C?#7.1 J1.D4(GBTCLK0-M2C_P)
NetC?#8_1: C?#8.1 J1.D5(GBTCLK0-M2C_N)

Not connected (* = marked no-connect by the designer): J1 D34(TRST_L)*

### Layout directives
differential pair: FMC_CLK0_M2C_N, FMC_CLK0_M2C_P, FMC_CLK1_M2C_N, FMC_CLK1_M2C_P, FMC_LA00_CC_N, FMC_LA00_CC_P, FMC_LA01_CC_N, FMC_LA01_CC_P, FMC_LA02_N, FMC_LA02_P, FMC_LA03_N, FMC_LA03_P, FMC_LA04_N, FMC_LA04_P, FMC_LA05_N, FMC_LA05_P, FMC_LA06_N, FMC_LA06_P, FMC_LA07_N, FMC_LA07_P, FMC_LA08_N, FMC_LA08_P, FMC_LA09_N, FMC_LA09_P, FMC_LA10_N, FMC_LA10_P, FMC_LA11_N, FMC_LA11_P, FMC_LA12_N, FMC_LA12_P, FMC_LA13_N, FMC_LA13_P, FMC_LA14_N, FMC_LA14_P, FMC_LA15_N, FMC_LA15_P, FMC_LA16_N, FMC_LA16_P, FMC_LA17_CC_N, FMC_LA17_CC_P, FMC_LA18_CC_N, FMC_LA18_CC_P, FMC_LA19_N, FMC_LA19_P, FMC_LA20_N, FMC_LA20_P, FMC_LA21_N, FMC_LA21_P, FMC_LA22_N, FMC_LA22_P, FMC_LA23_N, FMC_LA23_P, FMC_LA24_N, FMC_LA24_P, FMC_LA25_N, FMC_LA25_P, FMC_LA26_N, FMC_LA26_P, FMC_LA27_N, FMC_LA27_P, FMC_LA28_N, FMC_LA28_P, FMC_LA29_N, FMC_LA29_P, FMC_LA30_N, FMC_LA30_P, FMC_LA31_N, FMC_LA31_P, FMC_LA32_N, FMC_LA32_P, FMC_LA33_N, FMC_LA33_P, FMC_MGT_C2M_N, FMC_MGT_C2M_P, FMC_MGT_CLK_N, FMC_MGT_CLK_P, FMC_MGT_M2C_N, FMC_MGT_M2C_P

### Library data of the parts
C?#7 C?#8 = Cap: Capacitor
J1 = ASP-134603-01: 0.050" PITCH SOCKET ARRAY ASSEMBLY.; MANUFACTURER: SAMTEC
R?#21 R?#22 = Res: Resistor

## Sheet FPGA_Banks1.SchDoc
size A4
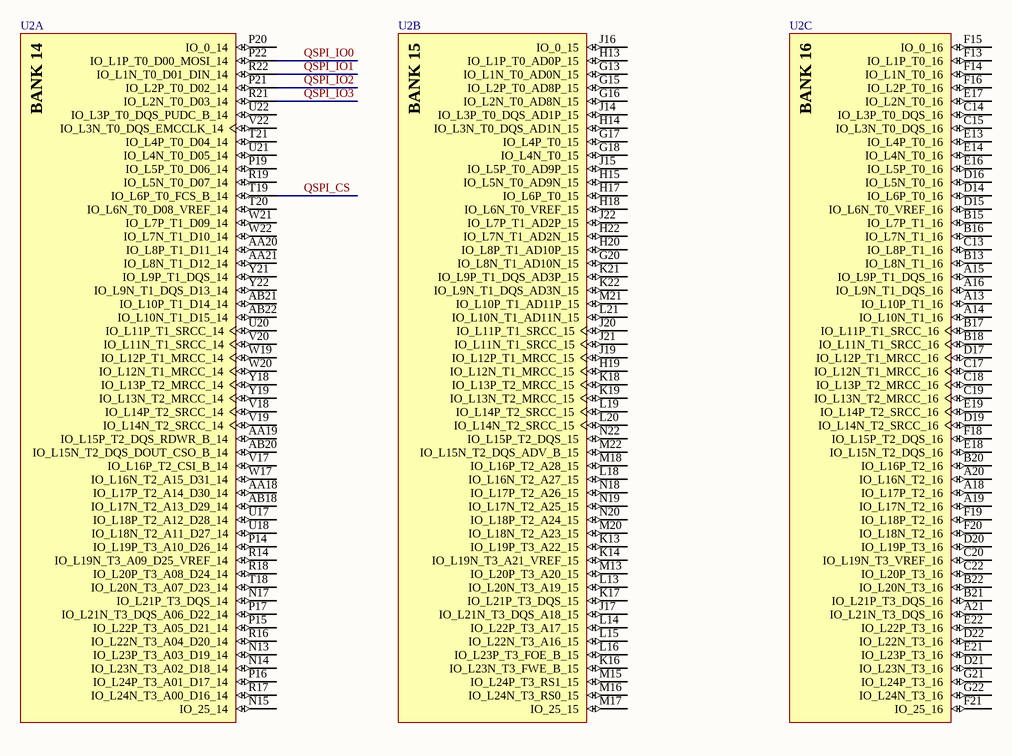
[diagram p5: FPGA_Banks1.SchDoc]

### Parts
U2  (no value)  [FGG484]  (parts A,B,C of 12)

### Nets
QSPI_CS: U2.T19(IO_L6P_T0_FCS_B_14)
QSPI_IO0: U2.P22(IO_L1P_T0_D00_MOSI_14)
QSPI_IO1: U2.R22(IO_L1N_T0_D01_DIN_14)
QSPI_IO2: U2.P21(IO_L2P_T0_D02_14)
QSPI_IO3: U2.R21(IO_L2N_T0_D03_14)

Not connected (* = marked no-connect by the designer): U2 A13(IO_L10P_T1_16) A14(IO_L10N_T1_16) A15(IO_L9P_T1_DQS_16) A16(IO_L9N_T1_DQS_16) A18(IO_L17P_T2_16) A19(IO_L17N_T2_16) A20(IO_L16N_T2_16) A21(IO_L21N_T3_DQS_16) AA18(IO_L17P_T2_A14_D30_14) AA19(IO_L15P_T2_DQS_RDWR_B_14) AA20(IO_L8P_T1_D11_14) AA21(IO_L8N_T1_D12_14) AB18(IO_L17N_T2_A13_D29_14) AB20(IO_L15N_T2_DQS_DOUT_CSO_B_14) AB21(IO_L10P_T1_D14_14) AB22(IO_L10N_T1_D15_14) B13(IO_L8N_T1_16) B15(IO_L7P_T1_16) B16(IO_L7N_T1_16) B17(IO_L11P_T1_SRCC_16) B18(IO_L11N_T1_SRCC_16) B20(IO_L16P_T2_16) B21(IO_L21P_T3_DQS_16) B22(IO_L20N_T3_16) C13(IO_L8P_T1_16) C14(IO_L3P_T0_DQS_16) C15(IO_L3N_T0_DQS_16) C17(IO_L12N_T1_MRCC_16) C18(IO_L13P_T2_MRCC_16) C19(IO_L13N_T2_MRCC_16) C20(IO_L19N_T3_VREF_16) C22(IO_L20P_T3_16) D14(IO_L6P_T0_16) D15(IO_L6N_T0_VREF_16) D16(IO_L5N_T0_16) D17(IO_L12P_T1_MRCC_16) D19(IO_L14N_T2_SRCC_16) D20(IO_L19P_T3_16) D21(IO_L23N_T3_16) D22(IO_L22N_T3_16) E13(IO_L4P_T0_16) E14(IO_L4N_T0_16) E16(IO_L5P_T0_16) E17(IO_L2N_T0_16) E18(IO_L15N_T2_DQS_16) E19(IO_L14P_T2_SRCC_16) E21(IO_L23P_T3_16) E22(IO_L22P_T3_16) F13(IO_L1P_T0_16) F14(IO_L1N_T0_16) F15(IO_0_16) F16(IO_L2P_T0_16) F18(IO_L15P_T2_DQS_16) F19(IO_L18P_T2_16) F20(IO_L18N_T2_16) F21(IO_25_16) G13(IO_L1N_T0_AD0N_15) G15(IO_L2P_T0_AD8P_15) G16(IO_L2N_T0_AD8N_15) G17(IO_L4P_T0_15) G18(IO_L4N_T0_15) G20(IO_L8N_T1_AD10N_15) G21(IO_L24P_T3_16) G22(IO_L24N_T3_16) H13(IO_L1P_T0_AD0P_15) H14(IO_L3N_T0_DQS_AD1N_15) H15(IO_L5N_T0_AD9N_15) H17(IO_L6P_T0_15) H18(IO_L6N_T0_VREF_15) H19(IO_L12N_T1_MRCC_15) H20(IO_L8P_T1_AD10P_15) H22(IO_L7N_T1_AD2N_15) J14(IO_L3P_T0_DQS_AD1P_15) J15(IO_L5P_T0_AD9P_15) J16(IO_0_15) J17(IO_L21N_T3_DQS_A18_15) J19(IO_L12P_T1_MRCC_15) J20(IO_L11P_T1_SRCC_15) J21(IO_L11N_T1_SRCC_15) J22(IO_L7P_T1_AD2P_15) K13(IO_L19P_T3_A22_15) K14(IO_L19N_T3_A21_VREF_15) K16(IO_L23N_T3_FWE_B_15) K17(IO_L21P_T3_DQS_15) K18(IO_L13P_T2_MRCC_15) K19(IO_L13N_T2_MRCC_15) K21(IO_L9P_T1_DQS_AD3P_15) K22(IO_L9N_T1_DQS_AD3N_15) L13(IO_L20N_T3_A19_15) L14(IO_L22P_T3_A17_15) L15(IO_L22N_T3_A16_15) L16(IO_L23P_T3_FOE_B_15) L18(IO_L16N_T2_A27_15) L19(IO_L14P_T2_SRCC_15) L20(IO_L14N_T2_SRCC_15) L21(IO_L10N_T1_AD11N_15) M13(IO_L20P_T3_A20_15) M15(IO_L24P_T3_RS1_15) M16(IO_L24N_T3_RS0_15) M17(IO_25_15) M18(IO_L16P_T2_A28_15) M20(IO_L18N_T2_A23_15) M21(IO_L10P_T1_AD11P_15) M22(IO_L15N_T2_DQS_ADV_B_15) N13(IO_L23P_T3_A03_D19_14) N14(IO_L23N_T3_A02_D18_14) N15(IO_25_14) N17(IO_L21P_T3_DQS_14) N18(IO_L17P_T2_A26_15) N19(IO_L17N_T2_A25_15) N20(IO_L18P_T2_A24_15) N22(IO_L15P_T2_DQS_15) P14(IO_L19P_T3_A10_D26_14) P15(IO_L22P_T3_A05_D21_14) P16(IO_L24P_T3_A01_D17_14) P17(IO_L21N_T3_DQS_A06_D22_14) P19(IO_L5P_T0_D06_14) P20(IO_0_14) R14(IO_L19N_T3_A09_D25_VREF_14) R16(IO_L22N_T3_A04_D20_14) R17(IO_L24N_T3_A00_D16_14) R18(IO_L20P_T3_A08_D24_14) R19(IO_L5N_T0_D07_14) T18(IO_L20N_T3_A07_D23_14) T20(IO_L6N_T0_D08_VREF_14) T21(IO_L4P_T0_D04_14) U17(IO_L18P_T2_A12_D28_14) U18(IO_L18N_T2_A11_D27_14) U20(IO_L11P_T1_SRCC_14) U21(IO_L4N_T0_D05_14) U22(IO_L3P_T0_DQS_PUDC_B_14) V17(IO_L16P_T2_CSI_B_14) V18(IO_L14P_T2_SRCC_14) V19(IO_L14N_T2_SRCC_14) V20(IO_L11N_T1_SRCC_14) V22(IO_L3N_T0_DQS_EMCCLK_14) W17(IO_L16N_T2_A15_D31_14) W19(IO_L12P_T1_MRCC_14) W20(IO_L12N_T1_MRCC_14) W21(IO_L7P_T1_D09_14) W22(IO_L7N_T1_D10_14) Y18(IO_L13P_T2_MRCC_14) Y19(IO_L13N_T2_MRCC_14) Y21(IO_L9P_T1_DQS_14) Y22(IO_L9N_T1_DQS_D13_14)

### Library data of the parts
U2 = XC7A35T-1FGG484C: as U2 on sheet FPGA_PWR

## Sheet FPGA_Banks2.SchDoc
size A4
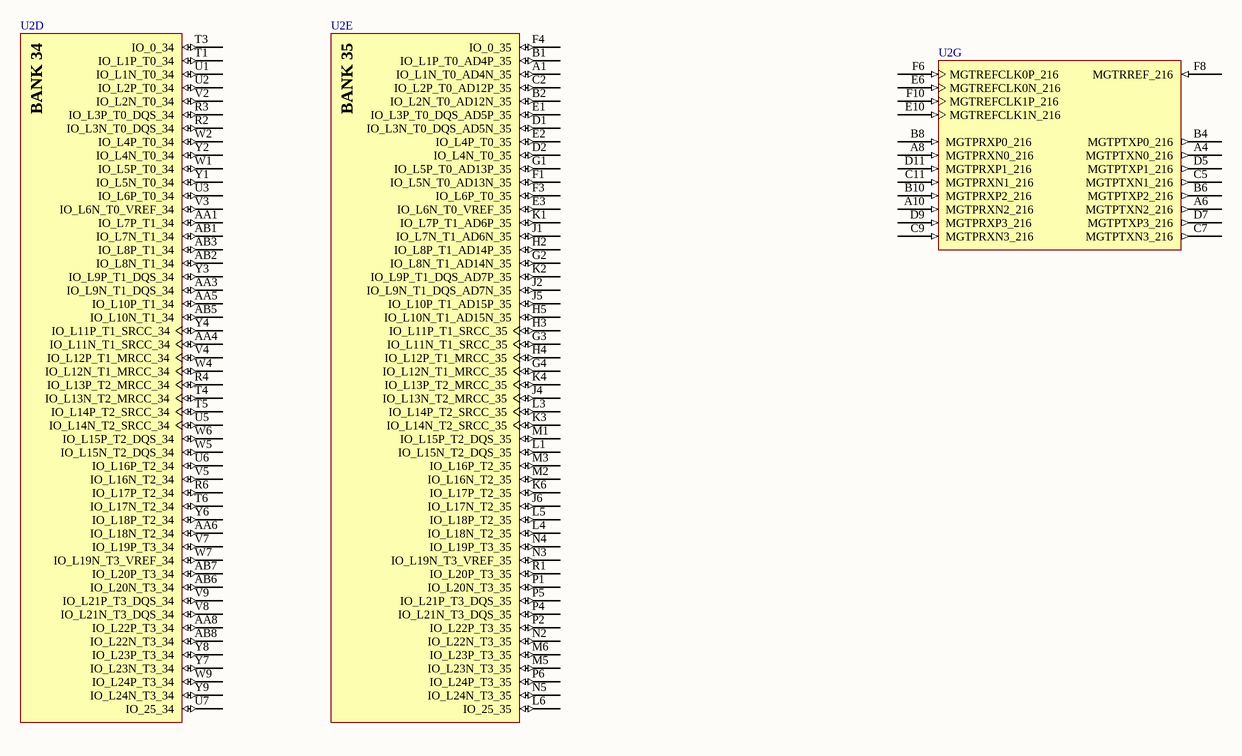
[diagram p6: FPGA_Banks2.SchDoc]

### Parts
U2  (no value)  [FGG484]  (parts D,E,G of 12)

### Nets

Not connected (* = marked no-connect by the designer): U2 A1(IO_L1N_T0_AD4N_35) A4(MGTPTXN0_216) A6(MGTPTXN2_216) A8(MGTPRXN0_216) A10(MGTPRXN2_216) AA1(IO_L7P_T1_34) AA3(IO_L9N_T1_DQS_34) AA4(IO_L11N_T1_SRCC_34) AA5(IO_L10P_T1_34) AA6(IO_L18N_T2_34) AA8(IO_L22P_T3_34) AB1(IO_L7N_T1_34) AB2(IO_L8N_T1_34) AB3(IO_L8P_T1_34) AB5(IO_L10N_T1_34) AB6(IO_L20N_T3_34) AB7(IO_L20P_T3_34) AB8(IO_L22N_T3_34) B1(IO_L1P_T0_AD4P_35) B2(IO_L2N_T0_AD12N_35) B4(MGTPTXP0_216) B6(MGTPTXP2_216) B8(MGTPRXP0_216) B10(MGTPRXP2_216) C2(IO_L2P_T0_AD12P_35) C5(MGTPTXN1_216) C7(MGTPTXN3_216) C9(MGTPRXN3_216) C11(MGTPRXN1_216) D1(IO_L3N_T0_DQS_AD5N_35) D2(IO_L4N_T0_35) D5(MGTPTXP1_216) D7(MGTPTXP3_216) D9(MGTPRXP3_216) D11(MGTPRXP1_216) E1(IO_L3P_T0_DQS_AD5P_35) E2(IO_L4P_T0_35) E3(IO_L6N_T0_VREF_35) E6(MGTREFCLK0N_216) E10(MGTREFCLK1N_216) F1(IO_L5N_T0_AD13N_35) F3(IO_L6P_T0_35) F4(IO_0_35) F6(MGTREFCLK0P_216) F8(MGTRREF_216) F10(MGTREFCLK1P_216) G1(IO_L5P_T0_AD13P_35) G2(IO_L8N_T1_AD14N_35) G3(IO_L11N_T1_SRCC_35) G4(IO_L12N_T1_MRCC_35) H2(IO_L8P_T1_AD14P_35) H3(IO_L11P_T1_SRCC_35) H4(IO_L12P_T1_MRCC_35) H5(IO_L10N_T1_AD15N_35) J1(IO_L7N_T1_AD6N_35) J2(IO_L9N_T1_DQS_AD7N_35) J4(IO_L13N_T2_MRCC_35) J5(IO_L10P_T1_AD15P_35) J6(IO_L17N_T2_35) K1(IO_L7P_T1_AD6P_35) K2(IO_L9P_T1_DQS_AD7P_35) K3(IO_L14N_T2_SRCC_35) K4(IO_L13P_T2_MRCC_35) K6(IO_L17P_T2_35) L1(IO_L15N_T2_DQS_35) L3(IO_L14P_T2_SRCC_35) L4(IO_L18N_T2_35) L5(IO_L18P_T2_35) L6(IO_25_35) M1(IO_L15P_T2_DQS_35) M2(IO_L16N_T2_35) M3(IO_L16P_T2_35) M5(IO_L23N_T3_35) M6(IO_L23P_T3_35) N2(IO_L22N_T3_35) N3(IO_L19N_T3_VREF_35) N4(IO_L19P_T3_35) N5(IO_L24N_T3_35) P1(IO_L20N_T3_35) P2(IO_L22P_T3_35) P4(IO_L21N_T3_DQS_35) P5(IO_L21P_T3_DQS_35) P6(IO_L24P_T3_35) R1(IO_L20P_T3_35) R2(IO_L3N_T0_DQS_34) R3(IO_L3P_T0_DQS_34) R4(IO_L13P_T2_MRCC_34) R6(IO_L17P_T2_34) T1(IO_L1P_T0_34) T3(IO_0_34) T4(IO_L13N_T2_MRCC_34) T5(IO_L14P_T2_SRCC_34) T6(IO_L17N_T2_34) U1(IO_L1N_T0_34) U2(IO_L2P_T0_34) U3(IO_L6P_T0_34) U5(IO_L14N_T2_SRCC_34) U6(IO_L16P_T2_34) U7(IO_25_34) V2(IO_L2N_T0_34) V3(IO_L6N_T0_VREF_34) V4(IO_L12P_T1_MRCC_34) V5(IO_L16N_T2_34) V7(IO_L19P_T3_34) V8(IO_L21N_T3_DQS_34) V9(IO_L21P_T3_DQS_34) W1(IO_L5P_T0_34) W2(IO_L4P_T0_34) W4(IO_L12N_T1_MRCC_34) W5(IO_L15N_T2_DQS_34) W6(IO_L15P_T2_DQS_34) W7(IO_L19N_T3_VREF_34) W9(IO_L24P_T3_34) Y1(IO_L5N_T0_34) Y2(IO_L4N_T0_34) Y3(IO_L9P_T1_DQS_34) Y4(IO_L11P_T1_SRCC_34) Y6(IO_L18P_T2_34) Y7(IO_L23N_T3_34) Y8(IO_L23P_T3_34) Y9(IO_L24N_T3_34)

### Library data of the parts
U2 = XC7A35T-1FGG484C: as U2 on sheet FPGA_PWR

## Sheet Regulators.SchDoc
size A4
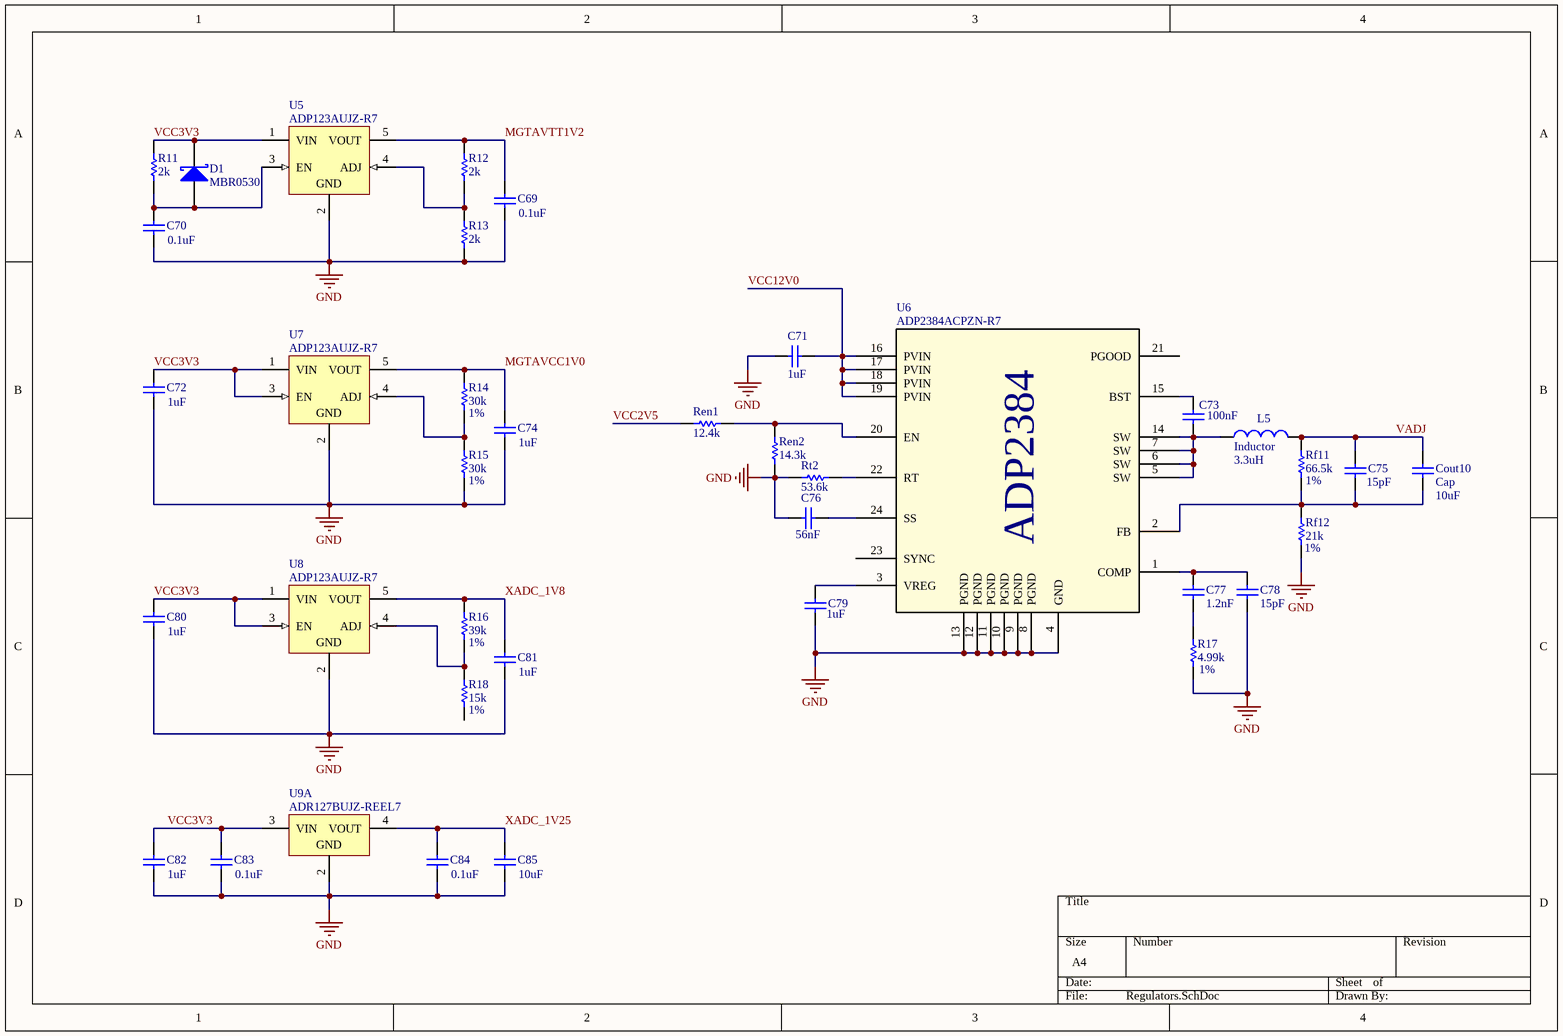
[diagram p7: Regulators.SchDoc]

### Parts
C69  value 0.1uF  [C0603]
C70  value 0.1uF  [C0603]
C71  value 1uF  [C0603]
C72  value 1uF  [C0603]
C73  value 100nF  [C0603]  (hidden comment: Cap)
C74  value 1uF  [C0603]
C75  value 15pF  [C0603]
C76  value 56nF  [C0603]
C77  value 1.2nF  [C0603]
C78  value 15pF  [C0603]
C79  value 1uF  [C0603]
C80  value 1uF  [C0603]
C81  value 1uF  [C0603]
C82  value 1uF  [C0603]
C83  value 0.1uF  [C0603]
C84  value 0.1uF  [C0603]
C85  value 10uF  [C0603]
Cout10  Cap  value 10uF  [C0805]
D1  MBR0530  [SOD-123]
L5  Inductor  value 3.3uH  [SD43]
R11  value 2k  [R0603]  (hidden comment: Res)
R12  value 2k  [R0603]  (hidden comment: Res)
R13  value 2k  [R0603]  (hidden comment: Res)
R14  value 30k  Tolerance: 1%  [R0603]  (hidden comment: Res)
R15  value 30k  Tolerance: 1%  [R0603]  (hidden comment: Res)
R16  value 39k  Tolerance: 1%  [R0603]  (hidden comment: Res)
R17  value 4.99k  Tolerance: 1%  [R0603]  (hidden comment: Res)
R18  value 15k  Tolerance: 1%  [R0603]  (hidden comment: Res)
Ren1  value 12.4k  [R0603]  (hidden comment: Res)
Ren2  value 14.3k  [R0603]  (hidden comment: Res)
Rf11  value 66.5k  Tolerance: 1%  [R0603]  (hidden comment: Res)
Rf12  value 21k  Tolerance: 1%  [R0603]  (hidden comment: Res)
Rt2  value 53.6k  [R0603]  (hidden comment: Res)
U5  ADP123AUJZ-R7  [ADI-UJ-5_N]
U6  ADP2384ACPZN-R7  [CP_24_12]
U7  ADP123AUJZ-R7  [ADI-UJ-5_N]
U8  ADP123AUJZ-R7  [ADI-UJ-5_N]
U9  ADR127BUJZ-REEL7  [ADI-UJ-6_N]  (part A of 2)

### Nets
GND: C69.2 C70.2 C71.2 C72.2 C74.2 C76.2 C78.2 C79.1 C80.2 C81.2 C82.2 C83.2 C84.2 C85.2 R13.1 R15.1 R17.1 Ren2.1 Rf12.1 Rt2.1 U5.2(GND) U6.4(GND) U6.8(PGND) U6.9(PGND) U6.10(PGND) U6.11(PGND) U6.12(PGND) U6.13(PGND) U7.2(GND) U8.2(GND) U9.2(GND)
MGTAVCC1V0: C74.1 R14.2 U7.5(VOUT)
MGTAVTT1V2: C69.1 R12.2 U5.5(VOUT)
VADJ: C75.1 Cout10.2 L5.2 Rf11.2
VCC2V5: Ren1.1
VCC3V3: C72.1 C80.1 C82.1 C83.1 D1.1(K) R11.2 U5.1(VIN) U7.1(VIN) U7.3(EN) U8.1(VIN) U8.3(EN) U9.3(VIN)
VCC12V0: C71.1 U6.16(PVIN) U6.17(PVIN) U6.18(PVIN) U6.19(PVIN)
XADC_1V8: C81.1 R16.2 U8.5(VOUT)
XADC_1V25: C84.1 C85.1 U9.4(VOUT)
NetC70_1: C70.1 D1.2(A) R11.1 U5.3(EN)
NetC73_1: C73.1 L5.1 U6.5(SW) U6.6(SW) U6.7(SW) U6.14(SW)
NetC73_2: C73.2 U6.15(BST)
NetC75_2: C75.2 Cout10.1 Rf11.1 Rf12.2 U6.2(FB)
NetC76_1: C76.1 U6.24(SS)
NetC77_1: C77.1 C78.1 U6.1(COMP)
NetC77_2: C77.2 R17.2
NetC79_2: C79.2 U6.3(VREG)
NetR12_1: R12.1 R13.2 U5.4(ADJ)
NetR14_1: R14.1 R15.2 U7.4(ADJ)
NetR16_1: R16.1 R18.2 U8.4(ADJ)
NetRen1_2: Ren1.2 Ren2.2 U6.20(EN)
NetRt2_2: Rt2.2 U6.22(RT)

Not connected (* = marked no-connect by the designer): R18 1; U6 21(PGOOD) 23(SYNC)

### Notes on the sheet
- (near U6) ADP2384

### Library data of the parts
C69-C85 Cout10 = Cap: Capacitor
L5 = Inductor: Code_IEC: 1005
R11-R18 Ren1 Ren2 Rf11 Rf12 Rt2 = Res: Resistor
U5 U7 U8 = ADP123AUJZ-R7: 300 mA, Low Quiescent Current, CMOS Linear Regulator, 2.3 to 5.5 V Vin, 0.8 to 5 V Vout, Industrial, 5-pin SOT23 (UJ-5), Reel; Manufacturer: Analog Devices; Iout max: 300mA; Supply Current IGND @ Small Load: 45uA; Vin (max) (V): 5.5; Vin (min) (V): 2.3; Vout Adjustable Range: 0.8V to 5V
U6 = ADP2384ACPZN-R7: Imported
U9 = ADR127BUJZ-REEL7: Precision, Micropower LDO Voltage Reference in TSOT, 1.25 V Output, 2.7 to 18 V Supply, Industrial, 6-pin SOT23 (UJ-6), Reel; Manufacturer: Analog Devices; Max V Supply (V): 18; Min V Supply (V): 2.7; Ref Out TC (ppm/C): 3; Vout: 1.25V

## Sheet Config.SchDoc
size A4
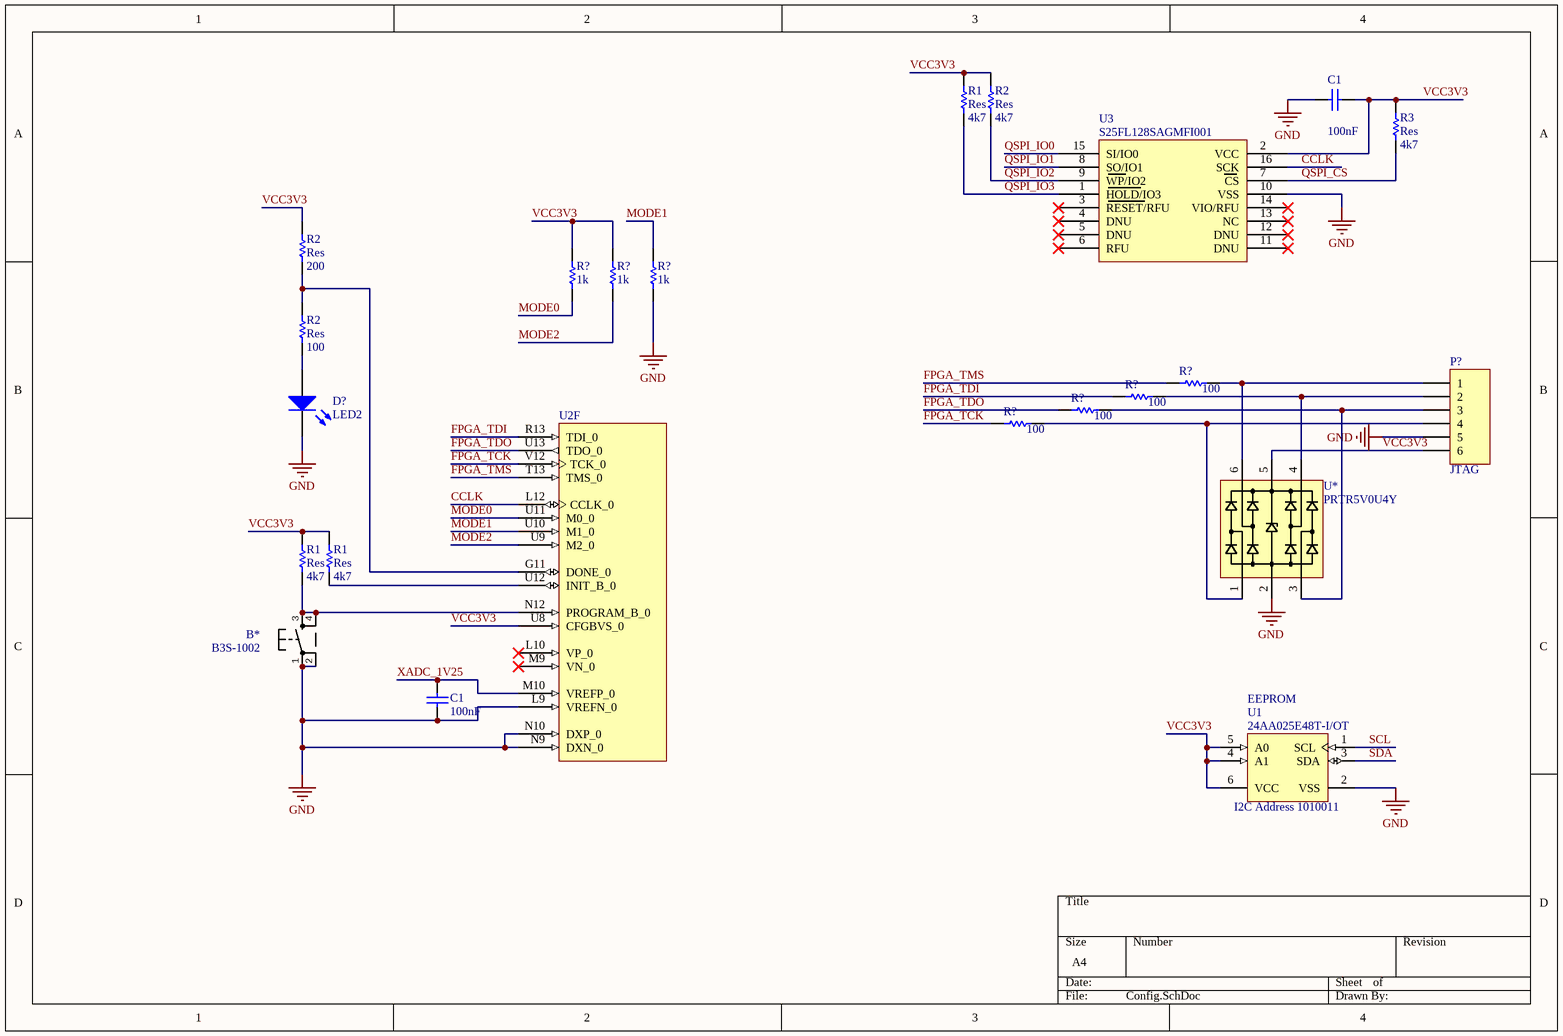
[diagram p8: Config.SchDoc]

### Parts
(Parts that share a designator on the sheet are numbered #1, #2 ... from top to bottom, then left to right.)
B*  B3S-1002  [B3S-1002]
C1#1  value 100nF  [C0603]  (hidden comment: Cap)
C1#2  value 100nF  [C0402]  (hidden comment: Cap)
D?#5  LED2  [3.2X1.6X1.1]
P?#2  JTAG  [HDR1X6]
R1#1  Res  value 4k7  [R0603]
R1#2  Res  value 4k7  [R0603]
R1#3  Res  value 4k7  [R0603]
R2#1  Res  value 4k7  [R0603]
R2#2  Res  value 200  [R0603]
R2#3  Res  value 100  [R0603]
R3  Res  value 4k7  [R0603]
R?#23  value 1k  [R0402]  (hidden comment: Res)
R?#24  value 1k  [R0402]  (hidden comment: Res)
R?#25  value 1k  [R0402]  (hidden comment: Res)
R?#26  value 100  [R0402]  (hidden comment: Res)
R?#27  value 100  [R0402]  (hidden comment: Res)
R?#28  value 100  [R0402]  (hidden comment: Res)
R?#29  value 100  [R0402]  (hidden comment: Res)
U1  24AA025E48T-I/OT  [MCHP-SOT-23-OT6_N]
U2  (no value)  [FGG484]  (part F of 12)
U3  S25FL128SAGMFI001  [SOIC16]
U*  PRTR5V0U4Y  [SOT363]

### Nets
GND: B*.1 B*.2 C1#1.1 C1#2.1 D?#5.2(K) P?#2.5 R?#25.1 U1.2(VSS) U2.L9(VREFN_0) U2.N9(DXN_0) U2.N10(DXP_0) U3.10(VSS) U*.2
CCLK: U2.L12(CCLK_0) U3.16(SCK)
FPGA_TCK: R?#29.1 U2.V12(TCK_0)
FPGA_TDI: R?#27.1 U2.R13(TDI_0)
FPGA_TDO: R?#28.1 U2.U13(TDO_0)
FPGA_TMS: R?#26.1 U2.T13(TMS_0)
MODE0: R?#23.1 U2.U11(M0_0)
MODE1: R?#25.2 U2.U10(M1_0)
MODE2: R?#24.1 U2.U9(M2_0)
QSPI_CS: R3.1 U3.7(CS)
QSPI_IO0: U3.15(SI/IO0)
QSPI_IO1: U3.8(SO/IO1)
QSPI_IO2: R2#1.1 U3.9(WP/IO2)
QSPI_IO3: R1#1.1 U3.1(HOLD/IO3)
SCL: U1.1(SCL)
SDA: U1.3(SDA)
VCC3V3: C1#1.2 P?#2.6 R1#1.2 R1#2.2 R1#3.2 R2#1.2 R2#2.2 R3.2 R?#23.2 R?#24.2 U1.4(A1) U1.5(A0) U1.6(VCC) U2.U8(CFGBVS_0) U3.2(VCC) U*.5
XADC_1V25: C1#2.2 U2.M10(VREFP_0)
NetB*_3: B*.3 B*.4 R1#2.1 U2.N12(PROGRAM_B_0)
NetD?#5_1: D?#5.1(A) R2#3.1
NetP?#2_1: P?#2.1 R?#26.2 U*.6
NetP?#2_2: P?#2.2 R?#27.2 U*.4
NetP?#2_3: P?#2.3 R?#28.2 U*.3
NetP?#2_4: P?#2.4 R?#29.2 U*.1
NetR1#3_1: R1#3.1 U2.U12(INIT_B_0)
NetR2#2_1: R2#2.1 R2#3.2 U2.G11(DONE_0)

Not connected (* = marked no-connect by the designer): U2 L10(VP_0)* M9(VN_0)*; U3 3(RESET/RFU)* 4(DNU)* 5(DNU)* 6(RFU)* 11(DNU)* 12(DNU)* 13(NC)* 14(VIO/RFU)*

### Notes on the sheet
- (near U1) EEPROM
- (near U1) I2C Address 1010011

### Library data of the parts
B* = TS42
C1#1 C1#2 = Cap: Capacitor
D?#5 = LED2: Typical RED, GREEN, YELLOW, AMBER GaAs LED
P?#2 = Header 6: Header, 6-Pin
R1#1-R1#3 R2#1-R2#3 R3 R?#23-R?#29 = Res: Resistor
U1 = 24AA025E48T-I/OT: 2K bits I2C™ Serial EEPROM with EUI-48™ Node Identity, 1.7 to 5.5 V, 400 kHz, -40 to 85 degC, 6-pin SOT-23 (OT6), Tape and Reel; Manufacturer: Microchip
U2 = XC7A35T-1FGG484C: as U2 on sheet FPGA_PWR

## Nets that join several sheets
GND: PWR_APD5052 (46 pins), FPGA_PWR (155 pins), SFP (20 pins), IO (6 pins), FMC (63 pins), Regulators (31 pins), Config (13 pins)
MGTAVCC1V0: FPGA_PWR (8 pins), Regulators (C74.1 R14.2 U7.5)
MGTAVTT1V2: FPGA_PWR (9 pins), Regulators (C69.1 R12.2 U5.5)
QSPI_CS: FPGA_Banks1 (U2.T19), Config (R3.1 U3.7)
QSPI_IO0: FPGA_Banks1 (U2.P22), Config (U3.15)
QSPI_IO1: FPGA_Banks1 (U2.R22), Config (U3.8)
QSPI_IO2: FPGA_Banks1 (U2.P21), Config (R2#1.1 U3.9)
QSPI_IO3: FPGA_Banks1 (U2.R21), Config (R1#1.1 U3.1)
SCL: SFP (J2.5 J?.5), FMC (J1.C30), Config (U1.1)
SDA: SFP (J2.4 J?.4), FMC (J1.C31), Config (U1.3)
VADJ: FPGA_PWR (26 pins), FMC (J1.G39 J1.H40), Regulators (C75.1 Cout10.2 L5.2 Rf11.2)
VCC1V0: PWR_APD5052 (5 pins), FPGA_PWR (20 pins)
VCC1V5: PWR_APD5052 (Cout7.2 Cout8.2 L4.2 Rf7.2), FPGA_PWR (13 pins)
VCC1V8: PWR_APD5052 (5 pins), FPGA_PWR (13 pins)
VCC2V5: PWR_APD5052 (Cout9.2 Rf8.2 U4.7), FPGA_PWR (12 pins), Regulators (Ren1.1)
VCC3V3: PWR_APD5052 (7 pins), FPGA_PWR (29 pins), SFP (12 pins), IO (9 pins), FMC (7 pins), Regulators (12 pins), Config (16 pins)
VCC12V0: PWR_APD5052 (11 pins), FMC (J1.C35 J1.C37), Regulators (5 pins)
XADC_1V8: FPGA_PWR (C45.2 U2.K10), Regulators (C81.1 R16.2 U8.5)
XADC_1V25: Regulators (C84.1 C85.1 U9.4), Config (C1#2.2 U2.M10)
